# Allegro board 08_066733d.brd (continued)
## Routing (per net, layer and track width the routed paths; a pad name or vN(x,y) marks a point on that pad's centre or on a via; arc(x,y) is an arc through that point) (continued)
VDD_EXT: length 204.3
  TOP w0.14: U19.J10 48.21,36.93 v1(48.26,36.88) U19.K9 ; U19.P3 v1(51.56,33.88) ; v1(36.89,42.22) 37.47,42.22 R15.1 ; U2.7 v1(55.87,73.33) ; U19.N4 v1(49.97,34.38) U19.M4 ; U19.C6 v1(45.66,35.38) ; v1(39.5,42.22) 38.93,42.22 R14.1 ; U19.F5 v1(46.71,35.33) 46.66,35.38 U19.E6 ; U19.P5 v1(51.56,34.88)
  TOP w0.203: U1.H9 v1(32.22,54.94) ; U1.K14 v1(36.22,53.34) ; U1.H14 v1(35.42,54.94) ; U1.H13 v1(34.62,54.94) ; U1.M7 v1(30.62,51.74) ; U1.M14 v1(35.42,52.54) ; U1.H11 v1(33.02,54.94) ; U1.N7 v1(29.82,51.74) ; v1(29.82,54.14) 30.03,53.93 U1.K7 ; U1.N14 v1(35.42,51.74) ; U1.H7 v1(29.82,54.94)
  TOP w0.254: 54.87,68.97 U2.2 ; v2(30.48,14.99) 31.13,14.99 31.38,15.24 U16.15 ; 34.53,17.28 34.38,17.14 U16.4 ; U24.8 15.61,65.51 ; VR1.2 19.86,14.49 20.48,13.87 v1(20.48,13.5)
  TOP w0.267: 54.1,73.79 54.37,73.52 U2.10
  TOP w0.305: R75.1 57.78,21.21 v1(58.42,21.21) 59.19,21.21 R71.1 ; R30.1 v1(46.74,21.05) ; U17.3 47.07,15.17 C215.1 ; v1(37.97,33.78) 37.58,33.39 U25.14 ; v2(2.54,58.42) DS3.A ; U11.5 59.57,40.4 58.92,41.05 C180.1 58.8,41.2 v1(58.8,41.78) ; R136.1 v1(54.88,10.67) ; R136.1 54.22,10.02 53.72,9.52 53.72,7.56 53.98,7.31 U26.4 55.02,7.31 55.02,7.3 ; R136.1 v1(54.22,11.32) ; v1(58.8,28.07) 58.92,27.95 C182.1 58.93,27.3 59.56,26.67 59.56,25.73 U14.4 ; v1(54.22,5.19) R137.1 54.83,5.84 55.02,6.03 55.02,7.3 ; v1(56.52,7.28) C247.1 55.92,7.94 55.34,7.37 55.08,7.37 55.02,7.3 ; U22.14 31.67,33.39 v1(32,33.72) ; DS5.A 56.66,17.46 v1(58.04,17.46) ; 15.61,65.51 C179.1 v2(16.14,66.81) ; U18.3 56.46,57.98 56.77,58.28 56.77,59.69 56.58,59.88 U18.1 ; U12.14 25.77,38.59 26.29,39.12 v1(26.61,39.12) ; U13.5 59.5,30.79 v1(58.8,31.5) 58.8,32.27 C181.1 ; C218.1 42.93,14.99 43.1,15.17 U17.8 ; C64.1 v1(25.82,43.34) ; R29.1 v1(48.07,29.09) ; v2(4.45,58.42) DS2.A ; v1(21.15,44.07) 21.08,44.01 C157.1 ; v1(38.42,39.12) 37.89,39.12 37.58,38.81 U23.14 ; v1(24.22,43.34) C127.1 ; U4.2 v2(17.78,30.61) ; v2(6.35,58.42) DS1.A ; U21.14 25.84,33.34 v1(26.92,33.34) ; v2(5.71,80.9) 5.71,79.02 ; v1(5.71,8.38) R45.1 ; v1(32.22,43.34) C139.1 ; v2(16.89,78.74) 17.27,79.04 U7.14 ; v2(5.71,68.91) S1.C2 ; v2(6.35,99.57) DS8.A ; v2(19.3,9.65) R105.1 ; v2(4.45,99.57) DS7.A ; v1(22.62,43.34) C163.1 ; v1(21.22,43.34) 21.53,43.03 C80.1 ; v2(8.26,58.42) DS4.A ; v2(10.79,47.62) 10.79,47.62 R78.1 ; R70.1 v1(55.13,30.85) ; v1(32.07,39.12) 31.67,38.72 U20.14 ; R64.1 v2(12.51,67.75) ; v1(29.02,43.34) C135.1 ; R38.1 v1(53.23,19.69) ; C70.1 v1(30.62,43.34) ; v1(20.62,66.34) R60.1 ; v1(4.45,8.38) R41.1 ; v2(18.22,9.6) C210.1 ; v1(20.62,64.54) R61.1 ; v1(27.42,43.34) C143.1 ; v1(19.82,69.85) DS6.A
  TOP w0.381: U5.5 v2(15.5,42.86) ; U9.5 v2(19.82,42.86) ; U10.5 v2(11.18,42.86)
  TOP w0.508: v2(54.87,67.7) C254.1 54.87,68.97
  L2_PWR w0.508: TP1.1 57.45,63.87 ; TP1.1 55.32,63.87 ; TP1.1 55.32,61.74 ; TP1.1 57.45,61.74
  L4_SIG w0.381: v2(19.24,25.72) 19.75,25.21 19.75,17.4 20.48,16.66 v1(20.48,13.5) 19.3,12.32 v2(19.3,9.65) 19.25,9.6 v2(18.22,9.6)
  BOTTOM w0.14: v1(48.26,36.88) 47.73,36.88 C234.1 ; C235.1 v1(45.66,35.38)
  BOTTOM w0.305: C237.1 v1(51.56,33.88) ; v1(52.78,40.19) R63.1 R62.1 ; C239.1 31.42,38.73 31.81,39.12 v1(32.07,39.12) ; v1(32,33.72) 31.62,33.33 C241.1 ; C131.1 v1(24.22,43.34) ; C147.1 v1(41.91,42.86) ; C119.1 v1(42.99,42.86) ; v1(37.97,33.78) 37.84,33.78 37.52,33.46 C250.1 ; R121.1 v1(26.92,38.54) ; R46.1 v2(17.76,35.96) ; v1(26.61,39.12) 26.02,38.53 C238.1 ; v1(49.97,34.38) 49.97,33.66 49.65,33.33 C236.1 ; C233.1 v1(51.56,34.88) ; v2(20.64,32.07) 20.07,32.63 R114.1 ; v1(47.31,42.86) C115.1 ; v1(30.62,43.34) C95.1 ; v1(35.18,38.86) 35.18,38.52 R134.1 ; R87.1 v2(12.19,74.29) ; C85.1 v1(46.23,42.9) ; v1(21.15,44.7) 20.33,44.7 C54.1 20.33,44.07 v1(21.15,44.07) ; v1(22.22,34.32) 22.57,34.32 23.05,34.8 R119.1 ; v1(46.93,43.43) 47.74,43.43 C49.1 47.74,44.07 v1(46.93,44.07) ; v2(16.89,78.74) 16,78.74 C189.1 ; R81.1 v2(14.73,73.91) ; C111.1 v1(45.15,42.86) ; v1(29.82,54.94) C59.1 ; v1(35.42,54.94) 35.42,54.24 C90.1 ; C139.1 v1(32.22,43.34) ; v1(21.22,43.34) C103.1 ; R116.1 v1(33.91,28.2) ; v1(25.82,43.34) C99.1 ; v2(13.65,80.77) R83.1 ; R48.1 v2(10.92,37.09) ; v1(23.05,33.78) R122.1 ; v1(38.42,39.12) 38.17,39.12 C249.1 ; C135.1 v1(29.02,43.34) ; v2(12.19,79.88) R86.1 ; v1(44.07,42.86) 44.07,41.97 C107.1 ; C143.1 v1(27.42,43.34) ; v1(23.05,38.99) R118.1 ; R133.1 v1(26.92,33.34) 26.15,33.34 C240.1 ; C176.1 v2(17.78,30.61) ; C163.1 v1(22.62,43.34) ; R131.1 v1(23.05,28.84)
  BOTTOM w0.381: R47.1 v2(20.51,29.34) ; R132.1 v1(24.84,28.96) ; v2(16.57,25.72) 16.57,23.25 R143.1 ; C175.1 v2(19.82,42.86) ; v2(16.89,34.98) R139.1 ; Y5.4 C252.1 v2(16.14,31.62) ; Y6.4 15.31,27.34 C253.1 15.3,27.37 v2(16.12,27.37) ; v2(15.5,42.86) C173.1 ; R55.1 17.21,40.89 16.57,40.26 v2(16.57,39.56) ; v2(17.78,30.61) 16.92,29.74 R140.1 ; R51.1 v2(16.89,36.39) ; v2(11.18,42.86) 11.18,42.29 C174.1 ; v2(15.18,36.83) 15.18,36.01 C251.1 15.17,34.59 Y4.4 ; v1(36.65,34.22) 36.65,35 R138.1 36.5,35.11 R135.1 ; R53.1 v2(14.29,39.43) ; R120.1 25.15,34.54 v1(24.84,34.22)
  BOTTOM w0.508: v2(10.79,47.62) 9.65,48.77 9.65,57.02 v2(8.26,58.42) v2(6.35,58.42) v2(4.45,58.42) v2(2.54,58.42) 2.54,57.91 3.81,56.64 P6.1 ; R5.1 41.54,13.09 v2(41.53,13.08)
  vias: v2(8.26,6.98) v2(8.26,6.22) v2(10.16,6.98) v2(10.16,6.22) v2(17.46,26.86) v2(17.46,25.72) v2(18.35,26.86) v2(18.35,25.72) v2(19.24,26.86) v2(26.92,16.89) v2(26.92,16.13) v2(27.94,16.89) v2(27.94,16.13) v2(29.21,16.89) v2(29.21,16.13) v2(35.18,17.08) v2(35.81,16.64) v2(37.21,16.64) v2(39.5,13.08) v2(39.5,12.32) v2(39.5,11.56) v2(40.51,13.08) v2(40.51,12.32) v2(40.51,11.56) v2(41.53,12.32) v2(41.53,11.56) v2(52.33,73.41) v2(52.96,73.41) v2(57.91,63.12) v2(57.91,62.36) v2(57.91,61.59) v2(58.67,63.12) v2(58.67,62.36) v2(58.67,61.59)
VDD_INPUT: length 5.5
  BOTTOM w0.305: v2(12.83,19.43) 12.95,19.3 15.62,19.3 R96.1
  vias: v2(10.67,20.19) v2(10.67,19.43) v2(11.81,20.19) v2(11.81,19.43) v2(12.83,20.19) v2(23.24,19.43) v2(24.26,19.43) v2(25.27,19.43)
VDD_INT: length 117.1
  TOP w0.203: v1(35.42,49.34) U1.R13 ; U1.M10 v1(33.02,51.74) ; v1(33.02,53.34) U1.K10 ; U1.H10 v1(32.22,55.74) ; U1.U15 v1(37.02,47.74) ; U1.H8 v1(30.62,55.74) ; U1.M6 v1(29.02,52.54) ; U1.H12 v1(33.82,55.74) ; U1.R12 v1(34.62,49.34) ; U1.K6 v1(29.02,54.14) ; U1.T7 v1(29.82,48.54) U1.T6 ; v1(29.82,49.34) U1.R7 ; U1.U7 v1(29.82,47.74) ; U1.P6 v1(29.02,50.94) ; U1.R14 v1(36.22,49.34) ; U1.R10 v1(32.22,49.34) ; v1(29.82,55.74) U1.H6 ; U1.G13 v1(35.42,56.54) U1.G14 ; v1(34.62,55.74) U1.G12 ; U1.R11 v1(33.82,49.34) ; U1.M12 v1(34.62,52.54) ; U1.K12 v1(33.82,53.34) U1.K11 ; U1.K15 v1(37.02,53.34) ; U1.H15 v1(37.02,55.74) ; U1.N15 v1(37.02,50.94) ; v1(30.62,49.34) U1.R8 ; U1.M15 v1(37.02,51.74) ; U1.P15 v1(37.02,50.14) ; v1(31.42,49.34) U1.R9 ; U1.K13 v1(34.62,53.34) ; U1.G6 v1(29.02,55.74) ; U1.T15 v1(37.02,48.54) ; U1.M11 v1(33.82,51.74) ; U1.N6 v1(29.02,51.74) ; U1.T14 v1(36.22,48.54) ; U1.M13 v1(34.62,51.74)
  TOP w0.305: v1(23.02,61.34) C120.1 ; v2(32.88,11.81) C208.1 ; v1(23.02,58.14) C60.1 ; C164.1 22.77,50.29 v1(23.02,50.54) ; C100.1 22.49,52.94 v1(23.02,52.94) ; v1(23.02,49.14) C104.1 ; R44.1 v2(1.91,8.38) ; R107.2 v2(35.94,9.52) ; v1(23.02,46.34) C86.1 ; v1(33.42,63.14) C93.1 ; v1(25.22,63.14) C78.1 ; v1(30.62,63.14) C83.1 ; v1(23.02,56.54) C116.1 ; C209.2 v2(37.21,9.52) ; R99.2 27.31,14.99 26.92,14.6 v2(26.92,13.59) ; v1(23.02,55.34) C91.1 ; v1(23.02,54.14) C96.1 ; v1(32.02,63.14) C88.1 ; v1(27.92,63.14) C73.1 ; v2(34.67,12) R101.1 ; v1(23.02,59.74) C81.1 ; v1(29.22,63.14) C68.1
  TOP w0.508: TP2.1 33.2,27.04 ; TP2.1 31.06,27.04 ; TP2.1 33.2,24.91 ; TP2.1 31.06,24.91
  L2_PWR w0.508: TP2.1 33.2,27.04 ; TP2.1 31.06,27.04 ; TP2.1 33.2,24.91 ; TP2.1 31.06,24.91
  BOTTOM w0.14: v1(33.82,49.34) 33.34,48.86 33.34,43.86 33.21,43.73 33.21,39.81 33.91,39.12 33.91,38.66 33.72,38.47 33.72,38.17 33.21,37.66 33.21,36.19 33.66,35.75 33.66,33.15 34.04,32.77 34.04,31.37 33.72,31.05 33.08,31.05 32.17,30.14 31.18,30.14 30.82,29.78 30.82,28.47 30.04,27.69 28.64,27.69 28.13,27.18 28.13,26.98 28.7,26.42 28.7,26.16
  BOTTOM w0.305: v1(29.82,49.34) 29.59,49.57 29.59,49.81 C152.1 ; v1(33.02,51.74) v1(33.82,51.74) v1(34.62,51.74) v1(34.62,52.54) v1(34.62,53.34) v1(33.82,53.34) v1(33.02,53.34) ; C60.1 v1(23.02,58.14) ; C50.1 18.92,50.54 v1(19.62,50.54) ; C164.1 22.77,50.29 v1(23.02,50.54) ; C132.1 31.62,49.78 31.62,49.54 v1(31.42,49.34) ; C136.1 36.22,49.7 v1(36.22,49.34) ; v1(30.62,49.34) C108.1 ; v1(37.02,53.34) v1(37.02,51.74) ; v2(1.91,8.38) v2(1.91,7.62) v2(1.02,7.62) v2(1.02,8.38) v2(1.02,9.14) v2(1.02,9.91) ; C96.1 v1(23.02,54.14) ; v2(14.22,54.61) 15.35,54.61 L1.1 15.31,53.98 v2(14.22,53.98) ; C100.1 22.49,52.94 v1(23.02,52.94) ; C212.1 28.7,25.53 28.7,26.16 ; v1(23.02,51.74) 22.84,51.56 C61.1 ; C76.1 36.12,56.54 v1(35.42,56.54) ; v1(29.02,55.74) C65.1 ; v1(23.02,47.74) C148.1 ; C55.1 17.35,56.34 17.65,56.04 v1(17.82,56.04) ; C128.1 35.42,49.7 v1(35.42,49.34) ; C120.1 v1(23.02,61.34) ; C91.1 v1(23.02,55.34) ; v1(33.82,55.74) C112.1 ; C81.1 v1(23.02,59.74) ; C116.1 v1(23.02,56.54) ; C104.1 v1(23.02,49.14) ; C71.1 v1(23.02,46.34)
  BOTTOM w0.508: TP2.1 33.2,27.04 ; TP2.1 31.06,24.91 ; TP2.1 33.2,24.91 ; TP2.1 31.06,27.04
  vias: v2(30.42,25.78) v2(30.86,26.99) v2(30.86,24.13) v2(32.13,24.13) v2(33.4,25.02) v2(33.4,24.13) v2(33.46,26.92) v2(33.85,25.78)
VDD_PLL: length 18.8
  TOP w0.305: U1.K8 v1(31.42,54.14) U1.K9 ; U1.M8 v1(31.42,52.54) U1.M9
  BOTTOM w0.305: C244.1 31.42,53.24 v1(31.42,52.54) 31.42,51.92 C46.1 ; C244.1 31.42,53.44 v1(31.42,54.14) ; C244.1 30.35,53.34 C242.1 30.11,53.34 24.36,53.34 C243.1 24.25,53.45 22.77,53.45 22.76,53.45 21.88,53.45 21.88,53.46 21.76,53.46 21.76,53.45 20.88,53.45 20.88,53.46 19.64,53.46 C47.1 17.89,53.44 L1.2
VDD_REF: length 206.1
  TOP w0.203: U1.P12 v1(34.62,50.14) ; U1.P11 v1(33.82,50.14) ; U1.P10 v1(32.22,50.14)
  TOP w0.305: C87.1 v1(46.22,45.34) ; v1(46.22,51.74) C77.1 ; v1(54.74,25.97) 54.74,25.38 R33.1 ; v1(6.98,8.26) R43.1 ; v1(3.17,8.38) R42.1 ; v1(46.22,48.54) C129.1 ; C109.1 34.99,43.71 v1(35.42,44.14) ; R39.1 v1(55.07,23.18) ; v1(43.02,45.34) C62.1 ; C82.1 v1(43.02,48.54) ; v1(46.22,50.14) C67.1 ; R32.1 v1(44.95,27.81) ; v1(33.82,43.34) C149.1 ; v1(43.02,50.14) C133.1 ; v1(46.22,46.94) C72.1
  TOP w0.508: v2(61.47,50.67) v2(61.47,51.43) ; v2(59.69,51.43) R16.1
  TOP w0.635: FL2.1 59.25,54.93 v2(59.69,54.48)
  L6_PWR w0.508: 60.02,57.99 TP4.1 62.15,57.99
  L7_SIG w0.305: v2(35.94,12) 35.94,15.05 35.37,15.62 34.66,15.62 34.35,15.93 34.35,18.61 34.29,18.67 34.29,21.27 35.67,22.65 35.67,33.51 35.14,34.04 35.14,37.15 36.8,38.82 36.8,40.86 35.75,41.91 35.75,43.81 v1(35.42,44.14)
  BOTTOM w0.305: v1(46.22,45.34) C125.1 ; v2(59.69,51.43) 59.69,50.55 58.8,49.66 56.9,49.66 53.4,46.16 53.4,44.7 49.66,40.96 49.66,39.55 49.35,39.24 ; C92.1 v1(46.22,51.74) ; C97.1 v1(43.02,45.34) ; C101.1 v1(46.22,46.94) ; C105.1 v1(46.22,50.14) ; C149.1 v1(33.82,43.34) ; v1(49.32,48.54) 50.12,48.54 C57.1 50.72,48.54 v1(51.62,48.54) ; C113.1 v1(43.02,50.14) ; C137.1 43.9,52.52 v1(43.92,52.54) ; v1(43.02,48.54) C145.1 ; v1(43.02,46.94) C121.1 ; C141.1 v1(46.22,48.54)
  BOTTOM w0.381: v1(35.42,44.14) 35.42,43.44 C52.1 36.22,43.44 v1(36.22,44.14) ; v1(3.17,8.38) 4,9.21 7.94,9.21 9.97,11.24 19.11,11.24 20.89,13.02 22.35,13.02 24.7,10.67 34.67,10.67 35.21,11.21 35.21,11.21 35.94,11.94 v2(35.94,12) ; 49.35,39.24 45.34,39.24 44.58,38.48 44.58,33.85 45.02,33.4 47.43,33.4 47.88,32.96 47.88,30.16 46.36,28.64 46.36,23.18 47.62,21.91 47.62,18.03 49.02,16.64 49.02,10.41 48.39,9.78 38.1,9.78 37.47,10.41 35.62,10.41 35.11,9.91 24.13,9.91 22.86,11.18 20.45,11.18 19.75,10.48 10.35,10.48 8.13,8.26 v1(6.98,8.26)
  vias: v2(60.45,57.53) v2(60.45,56.77) v2(60.45,56.01) v2(61.47,57.53) v2(61.47,56.77) v2(61.47,56.01)
AUDIO_CLK: length 74.8
  TOP w0.14: R36.2 v1(55.1,22.1)
  L8_SIG w0.127: v1(8.26,31.88) 10.2,31.88 12.17,29.91 18.2,29.91 21.33,26.78 26.73,26.78 30.28,23.24 33.53,23.24 34.48,24.19 34.48,26.18 35.64,27.34 37.1,27.34 37.29,27.53 37.29,28.1 38.47,29.29 43.45,29.29 44.91,30.75 50.81,30.75 51.12,31.05 51.94,31.05 52.2,30.8 52.2,30.23 50.67,28.7 50.67,22.88 51.92,21.63 52.69,21.63 53.15,22.1 v1(55.1,22.1)
  BOTTOM w0.14: J3.40 8.25,31.88 v1(8.26,31.88) 8.95,31.88 9.33,32.26 9.33,34.8 10.14,35.6 R141.2
CLK1: length 69
  TOP w0.14: R35.2 v1(52.08,28.38)
  L8_SIG w0.127: v1(10.99,35.12) 17.7,41.83 20.02,41.83 20.59,42.41 30.58,42.41 31.45,41.53 34.2,41.53 34.78,40.96 38.8,40.96 40.11,39.65 50.33,39.65 53.66,36.32 53.66,35.79 53.66,29.96 v1(52.08,28.38)
  BOTTOM w0.14: 9.97,31.37 10.22,31.62 10.22,34.35 v1(10.99,35.12) ; 9.97,31.37 10.22,31.11 10.22,29.34 10.38,29.18 R142.2 ; 9.97,31.37 6.91,31.37 J3.42
CLK2: length 65.9
  TOP w0.14: v1(50.35,18.92) 50.35,19.63 R37.2
  L4_SIG w0.127: v1(50.35,18.92) 50.35,19.82 49.75,20.42 48.48,20.42 47.62,21.27 47.62,26.03 v2(44.32,29.34)
  L8_SIG w0.127: v2(44.32,29.34) 43.94,28.96 38.61,28.96 37.62,27.97 37.62,27.4 37.24,27.01 35.78,27.01 34.81,26.04 34.81,24.06 33.66,22.91 30.14,22.91 26.63,26.42 21.21,26.42 18.82,28.8 13.4,28.8 12.72,29.49 9.63,29.49 v1(8.26,30.86)
  BOTTOM w0.14: J3.44 8,30.61 v1(8.26,30.86) 8.76,30.86 9.14,30.48 9.14,29.08 9.84,28.38 11.3,28.38 11.87,27.81 R144.2
CON_RESET_IN*: length 78.8
  TOP w0.14: U11.2 56.26,38.73 55.82,38.29 v1(54.61,38.29) 53.92,38.29 53.53,37.9 53.53,32 52.51,30.99 52.07,30.99 v1(51.5,30.42)
  L4_SIG w0.127: v1(8.51,14.22) 8.51,19.79 10.05,21.33 10.05,21.35 10.1,21.4 10.1,27.9 10.52,28.32 v2(12.19,28.32)
  L8_SIG w0.127: v2(12.19,28.32) 12.19,27.56 14.83,24.92 22.45,24.92 23.93,23.44 27.87,23.44 28.73,22.58 33.8,22.58 35.14,23.92 35.14,25.91 35.92,26.68 36.26,26.68 37.38,26.68 37.95,27.26 37.95,27.83 38.75,28.63 46.15,28.63 47.94,30.42 v1(51.5,30.42)
  BOTTOM w0.14: R62.2 v1(54.61,38.29) ; J3.96 6.91,14.22 v1(8.51,14.22)
DAI0_PIN01: length 55.7
  TOP w0.203: v1(35.42,47.74) U1.U13
  L4_SIG w0.127: v1(53.21,15.11) 50.61,15.11 47.24,18.48 47.24,23.43 44.45,26.23 44.45,28.32 43.73,29.04 43.73,29.88 44.69,30.85 44.69,37.22 42.56,39.36 42.56,40.98 41.14,42.43 41.14,43.47 39.84,44.77 39.15,44.77 39.02,44.89 39.02,47.14 38.82,47.34 35.82,47.34 v1(35.42,47.74)
  L8_SIG w0.127: v1(61.72,13.72) 61.09,14.35 53.98,14.35 v1(53.21,15.11)
  BOTTOM w0.14: J1.3 61.47,13.46 v1(61.72,13.72)
DAI0_PIN02: length 50
  TOP w0.203: v1(37.02,46.14) U1.W15
  L4_SIG w0.127: v1(58.8,13.59) 49.98,13.59 45.28,18.29 45.28,23.37 42.55,26.1 42.55,28.32 41.91,28.96 41.91,32.98 42.55,33.61 42.55,35.05 41.91,35.68 41.91,38.44 40.26,40.09 40.26,41.65 40.07,41.84 40.07,43.03 39.41,43.69 38.61,43.69 37.42,44.87 37.42,45.74 v1(37.02,46.14)
  BOTTOM w0.14: 59.31,14.1 59.31,14.1 ; 59.31,14.1 59.31,14.1 ; 59.31,14.1 J1.5 ; 59.31,14.1 v1(58.8,13.59)
DAI0_PIN03: length 47.7
  TOP w0.203: v1(37.82,45.34) U1.Y16
  L5_SIG w0.127: v1(37.82,45.34) 37.82,44.6 41.28,41.15 41.28,31.37 44.2,28.45 45.33,28.45 45.66,28.12 45.66,25.68 49.55,21.78 51.76,21.78 53.66,19.88 57.59,19.88 57.79,19.68 59.56,19.68 60.45,18.8 60.45,16.13 v1(61.72,14.86)
  BOTTOM w0.14: v1(61.72,14.86) 60.41,14.86 J1.7
DAI0_PIN04: length 62.5
  TOP w0.203: v1(35.42,46.14) U1.W13
  L4_SIG w0.127: v1(61.72,15.62) 61.09,14.99 61.09,12.83 58.42,10.16 54.74,10.16 52.2,12.7 49.47,12.7 41.85,20.32 40.7,20.32 36.55,24.47 36.55,26.39 40.87,30.71 40.87,37.93 39.18,39.62 39.18,40.58 35.81,43.94 35.81,45.75 v1(35.42,46.14)
  BOTTOM w0.14: v1(61.72,15.62) 61.47,15.37 J1.9
DAI0_PIN05: length 47.4
  TOP w0.203: v1(37.02,46.94) U1.V15
  L5_SIG w0.127: v1(58.8,15.87) 59.56,16.64 59.56,18.8 59.05,19.3 57.6,19.3 57.4,19.49 54.8,19.49 54.55,19.24 53.07,19.24 51.55,20.76 50.1,20.76 44.45,26.42 44.45,27.5 40.83,31.12 40.83,40 38.16,42.67 38.16,43.05 37.42,43.8 37.42,46.54 v1(37.02,46.94)
  BOTTOM w0.14: J1.11 58.93,16 v1(58.8,15.87)
DAI0_PIN06: length 51
  TOP w0.203: v1(38.62,45.34) U1.Y17
  L4_SIG w0.127: v1(58.8,16.76) 59.44,16.13 59.44,14.86 59.05,14.48 50.55,14.48 46.29,18.73 46.29,23.62 43.4,26.52 43.4,28.8 42.67,29.53 42.67,30.67 43.75,31.75 43.75,32.7 44.32,33.27 44.32,37.02 41.02,40.32 41.02,42.04 40.81,42.25 40.81,43.33 39.75,44.39 38.81,44.39 38.62,44.58 v1(38.62,45.34)
  BOTTOM w0.14: J1.13 58.93,16.64 v1(58.8,16.76)
DAI0_PIN07: length 53.7
  TOP w0.203: v1(37.82,46.14) U1.W16
  L4_SIG w0.127: v1(58.8,17.53) 59.94,16.38 59.94,14.73 59.31,14.1 50.16,14.1 45.79,18.47 45.79,23.49 42.99,26.29 42.99,28.51 42.29,29.21 42.29,32.89 42.98,33.58 42.98,35.1 42.24,35.84 42.24,38.57 40.64,40.17 40.64,41.85 40.45,42.04 40.45,43.22 39.61,44.06 38.68,44.06 38.22,44.52 38.22,45.74 v1(37.82,46.14)
  BOTTOM w0.14: J1.15 59.05,17.27 v1(58.8,17.53)
DAI0_PIN08: length 59.6
  TOP w0.203: v1(36.22,46.94) U1.V14
  L4_SIG w0.127: v1(36.22,46.94) 36.63,46.53 36.63,45.08 38.43,43.31 39.12,43.31 39.31,43.12 39.31,42.7 39.07,42.45 39.07,41.71 39.88,40.89 39.88,39.94 41.53,38.29 41.53,26.54 44.77,23.3 44.77,18.16 49.72,13.21 53.09,13.21 55.37,10.92 58.17,10.92 60.45,13.21 60.45,16.38 v1(61.72,17.65)
  BOTTOM w0.14: J1.17 61.47,17.91 v1(61.72,17.65)
DAI0_PIN09: length 49.6
  TOP w0.203: v1(35.42,48.54) U1.T13
  L5_SIG w0.127: v1(58.04,18.16) 56.96,17.08 48.83,17.08 45.28,20.64 45.28,23.12 40.07,28.33 40.07,36.32 37.08,39.31 37.08,40.96 35.82,42.22 35.82,48.14 v1(35.42,48.54)
  BOTTOM w0.14: J1.19 59.31,18.54 58.93,18.16 v1(58.04,18.16)
DAI0_PIN10: length 45.7
  TOP w0.203: v1(36.22,47.74) U1.U14
  L5_SIG w0.127: v1(58.04,18.8) 57.02,17.78 53.59,17.78 51.27,20.1 50.3,20.1 40.45,29.95 40.45,39.31 36.62,43.14 36.62,47.34 v1(36.22,47.74)
  BOTTOM w0.14: J1.21 60.15,19.3 58.55,19.3 v1(58.04,18.8)
DAI0_PIN11: length 44.6
  TOP w0.203: v1(37.82,46.94) U1.V16
  L5_SIG w0.127: v1(61.72,19.43) 60.45,20.7 55.69,20.7 54.93,21.46 54.48,21.46 52.45,23.49 49.06,23.49 46.1,26.46 46.1,29.21 44.77,30.54 44.77,32.64 42.53,34.87 42.53,40.65 38.22,44.97 38.22,46.54 v1(37.82,46.94)
  BOTTOM w0.14: v1(61.72,19.43) 61.34,19.81 J1.23
DAI0_PIN12: length 40.5
  TOP w0.203: v1(39.42,45.34) U1.Y18
  L5_SIG w0.127: v1(61.72,20.19) 60.2,21.72 56.64,21.72 55.75,22.61 54.99,22.61 53.53,24.07 53.53,24.7 52.64,25.59 50.21,25.59 45.29,30.51 45.29,33.09 44.2,34.19 44.2,39.72 39.42,44.49 v1(39.42,45.34)
  BOTTOM w0.14: v1(61.72,20.19) 61.47,20.45 J1.25
DAI0_PIN13: length 49.1
  TOP w0.203: v1(37.82,50.94) U1.N16
  L5_SIG w0.127: v1(61.72,20.95) 62.23,21.46 62.23,22.73 61.21,23.75 61.21,24.76 58.93,27.05 57.85,27.05 56.45,28.45 54.1,28.45 51.18,31.37 51.18,31.94 50.36,32.76 50.36,34.73 50.32,34.77 50.32,41.95 47.24,45.02 47.24,49.02 46.63,49.64 44.82,49.64 43.12,51.34 38.22,51.34 v1(37.82,50.94)
  BOTTOM w0.14: v1(61.72,20.95) 61.59,21.08 J1.27
DAI0_PIN14: length 46.5
  TOP w0.203: v1(38.62,49.34) U1.R17
  L5_SIG w0.127: v1(38.62,49.34) 39.02,48.94 41.66,48.94 41.93,49.21 43.15,49.21 44.02,48.34 44.02,45.14 45.58,43.58 45.58,39.99 45.15,39.56 45.15,34.8 46.48,33.46 46.48,31.43 50.3,27.61 52.65,27.61 54.1,26.16 54.1,25.46 55.13,24.43 56.46,24.43 58.04,22.86 60.58,22.86 v1(61.72,21.72)
  BOTTOM w0.14: v1(61.72,21.72) 61.72,21.72 ; 61.72,21.72 61.21,21.72 ; 61.72,21.72 61.21,21.72 ; 61.21,21.72 J1.29
DAI0_PIN15: length 46
  TOP w0.203: v1(38.62,50.14) U1.P17
  L5_SIG w0.127: v1(38.62,50.14) 39.02,50.54 41.02,50.54 41.22,50.74 43.06,50.74 43.26,50.54 44.52,49.28 46.36,49.28 46.86,48.77 46.86,44.89 49.72,42.04 49.72,34.86 49.4,34.54 49.4,31.88 54.17,27.11 55.18,27.11 55.44,27.37 56.83,27.37 v1(61.72,22.48)
  BOTTOM w0.14: v1(61.72,22.48) 61.6,22.35 J1.31
DAI0_PIN16: length 41.1
  TOP w0.203: v1(39.42,48.54) U1.T18
  L5_SIG w0.127: v1(39.42,48.54) 39.82,48.14 42.82,48.14 43.52,47.44 43.52,44.77 44.7,43.58 44.7,34.14 45.62,33.23 45.62,30.64 49.66,26.61 52.28,26.61 56.54,22.35 v1(58.42,22.35)
  BOTTOM w0.14: J1.33 59.06,22.99 v1(58.42,22.35)
DAI0_PIN17: length 41.2
  TOP w0.203: v1(39.42,49.34) U1.R18
  L5_SIG w0.127: v1(58.42,23.37) 55.42,26.37 54.95,26.37 54.59,26.73 54.04,26.73 52.83,27.94 50.48,27.94 49.85,28.57 49.85,29.53 47.75,31.62 47.75,34.51 47.24,35.02 47.24,39.62 46.66,40.21 46.66,43.07 44.35,45.38 44.35,48.78 43.54,49.59 41.87,49.59 41.72,49.74 39.82,49.74 v1(39.42,49.34)
  BOTTOM w0.14: v1(58.42,23.37) 58.67,23.62 J1.35
DAI0_PIN18: length 46.1
  TOP w0.203: v1(40.22,47.74) U1.U19
  L7_SIG w0.127: v1(57.79,48.51) 57.79,47.62 59.56,45.85 59.56,26.16 v1(61.72,24)
  L8_SIG w0.127: v1(57.79,48.51) 52.25,48.51 51.49,47.74 v1(40.22,47.74)
  BOTTOM w0.14: J1.37 61.47,24.26 v1(61.72,24)
DAI0_PIN19: length 45.3
  TOP w0.14: U1.Y19 40.86,44.7 55.11,44.7 56.89,46.48 v1(60.07,46.48)
  L7_SIG w0.127: v1(61.72,24.76) 60.07,26.42 v1(60.07,46.48)
  BOTTOM w0.14: J1.39 61.59,24.89 v1(61.72,24.76)
DAI0_PIN20: length 47.1
  TOP w0.203: v1(39.42,46.14) U1.W18
  L7_SIG w0.127: v1(60.07,47.24) 60.58,46.73 60.58,26.67 v1(61.72,25.53)
  L8_SIG w0.127: v1(39.42,46.14) 39.83,45.73 41.22,45.73 41.59,46.1 48.75,46.1 49.62,45.22 52.71,45.22 54.72,47.24 v1(60.07,47.24)
  BOTTOM w0.14: 61.21,25.53 J1.41 ; 61.21,25.53 v1(61.72,25.53) 61.72,25.53 61.21,25.53
DAI1_PIN01: length 52.1
  TOP w0.203: v1(37.82,52.54) U1.L16
  L5_SIG w0.127: v1(40.07,24.83) 40.96,23.94 42.35,23.94 44.64,21.65 44.64,20.38 51.94,13.08 v1(55.12,13.08)
  BOTTOM w0.14: J1.4 55.5,13.46 v1(55.12,13.08) ; v1(40.07,24.83) 40.73,25.49 40.73,27.43 40.41,27.75 40.41,42.9 38.22,45.09 38.22,52.14 v1(37.82,52.54)
DAI1_PIN02: length 56
  TOP w0.203: v1(41.02,54.94) U1.J20
  L4_SIG w0.127: v1(41.02,54.94) 44.69,54.94 45.37,54.26 47.21,54.26 50.16,51.31 50.16,43.31 51.17,42.3 51.17,38.77 53.7,36.23 54.7,36.23 56.11,34.82 56.11,24.56 55.98,24.43 55.04,24.43 54.55,23.94 54.55,22.02 57.02,19.55 57.02,16.89 v1(58.8,15.11)
  BOTTOM w0.14: J1.6 57.79,14.1 v1(58.8,15.11)
DAI1_PIN03: length 53.6
  TOP w0.203: v1(39.42,54.14) U1.K18
  L4_SIG w0.127: v1(39.42,54.14) 39.82,53.74 44.92,53.74 48.01,50.65 48.01,46.8 49.28,45.53 49.28,43.12 50.51,41.88 50.51,38.41 50.67,38.25 50.67,38.23 53.47,35.43 53.47,33.61 54.67,32.41 54.67,28.32 53.15,26.79 53.15,25.4 53.72,24.83 53.72,21.72 54.29,21.15 54.29,20.51 54.79,20.01 55.62,20.01 56.52,19.11 56.52,16.64 v1(58.04,15.11)
  BOTTOM w0.14: J1.8 57.66,14.73 v1(58.04,15.11)
DAI1_PIN04: length 51.1
  TOP w0.203: v1(38.62,52.54) U1.L17
  L4_SIG w0.127: v1(38.62,52.54) 39.02,52.14 42.92,52.14 44.26,50.8 44.26,45.87 45.49,44.64 47.12,44.64 47.5,44.26 47.5,43.43 49.39,41.54 49.39,38.07 52.48,34.98 52.48,33.2 53,32.68 53,28.11 51.31,26.42 51.31,25.57 51.67,25.2 51.67,21.89 54.42,19.14 54.42,15.81 v1(55.12,15.11)
  BOTTOM w0.14: v1(55.12,15.11) 55.37,15.37 J1.10
DAI1_PIN05: length 51.3
  TOP w0.203: v1(38.62,53.34) U1.L18
  L4_SIG w0.127: v1(38.62,53.34) U1.L18 42.72,52.94 44.77,50.89 44.77,46.86 45.78,45.85 46.42,45.85 48.12,44.15 48.12,43.32 49.77,41.67 49.77,38.15 52.81,35.12 52.81,33.34 53.33,32.82 53.33,27.9 51.67,26.25 51.67,25.67 52.01,25.33 52.01,22.77 52.83,21.95 52.83,21.23 54.51,19.56 55.5,19.56 55.75,19.3 55.75,16.64 v1(55.12,16)
  BOTTOM w0.14: J1.12 55.5,16 v1(55.12,16)
DAI1_PIN06: length 51
  TOP w0.203: v1(39.42,51.74) U1.M18
  L4_SIG w0.127: v1(39.42,51.74) 42.72,51.74 43.94,50.52 43.94,45.8 46.74,43 46.74,42.42 48.64,40.51 48.64,37.59 50.53,35.71 50.53,33.38 52.64,31.26 52.64,28.33 52.06,27.75 51.18,27.75 50.67,27.24 50.67,22.39 52.8,20.26 52.8,19.51 53.05,19.26 53.51,19.26 54.05,18.72 54.05,16.71 v1(53.21,15.87)
  BOTTOM w0.14: v1(53.21,15.87) 53.98,16.64 J1.14
DAI1_PIN07: length 48.8
  TOP w0.203: v1(39.42,50.94) U1.N18
  L4_SIG w0.127: v1(39.42,50.94) 39.82,50.54 41.28,50.54 41.75,50.07 41.75,46.01 44.5,43.26 44.5,42.88 46.86,40.51 46.86,37.02 47.12,36.77 47.12,34.89 46.82,34.59 46.82,33.57 49.21,31.18 50.13,31.18 51.18,30.12 51.18,28.77 49.29,26.87 49.29,25.95 48.58,25.24 48.58,22.57 53.05,18.1 53.53,18.1 53.72,17.91 53.72,17.14 v1(53.21,16.64)
  BOTTOM w0.14: v1(53.21,16.64) 53.59,17.02 55.12,17.02 55.38,17.27 J1.16
DAI1_PIN08: length 47
  TOP w0.203: v1(39.42,50.14) U1.P18
  L4_SIG w0.127: v1(53.21,17.53) 51.94,17.53 50.85,18.62 50.85,19.83 47.96,22.72 47.96,25.09 48.96,26.09 48.96,27.05 50.85,28.94 50.85,29.92 50.16,30.61 49.15,30.61 45.85,33.91 45.85,34.61 46.16,34.92 46.16,39.95 43.5,42.62 43.5,43.43 41.42,45.51 41.42,49.04 40.72,49.74 39.82,49.74 v1(39.42,50.14)
  BOTTOM w0.14: v1(53.21,17.53) 54.99,17.53 55.37,17.91 J1.18
DAI1_PIN09: length 47.3
  TOP w0.203: v1(38.62,51.74) U1.M17
  L8_SIG w0.127: v1(55.12,18.29) 53.09,18.29 51.82,19.56 50.8,19.56 49.97,20.38 48.2,20.38 43.75,24.83 v1(40.83,24.83)
  BOTTOM w0.14: v1(38.62,51.74) 39.02,51.34 39.02,45.05 40.75,43.32 40.75,27.89 41.07,27.57 41.07,25.07 v1(40.83,24.83) ; v1(55.12,18.29) 55.37,18.54 J1.20
DAI1_PIN10: length 46.3
  TOP w0.203: v1(37.82,51.74) U1.M16
  L8_SIG w0.127: v1(55.12,19.05) 54.04,19.05 53.85,19.24 52.71,19.24 51.94,20 50.86,20 49.59,21.28 48.06,21.28 43.82,25.53 42.01,25.53 v1(40.07,27.47)
  BOTTOM w0.14: J1.22 55.25,19.18 v1(55.12,19.05) ; v1(37.82,51.74) 37.42,51.34 37.42,44.94 40.07,42.29 v1(40.07,27.47)
DAI1_PIN11: length 49.6
  TOP w0.203: v1(38.62,50.94) U1.N17
  L4_SIG w0.127: v1(38.62,50.94) 39.02,51.34 42.52,51.34 43.56,50.3 43.56,45.34 45.72,43.18 45.72,42.61 48.26,40.07 48.26,37.43 48.65,37.04 48.65,35.5 47.75,34.61 47.75,33.53 48.13,33.15 50.23,33.15 52.01,31.37 52.01,29.12 49.66,26.77 49.66,22.03 52.9,18.8 v1(53.21,18.8)
  BOTTOM w0.14: v1(53.21,18.8) 54.36,19.81 J1.24
DAI1_PIN12: length 40.5
  TOP w0.203: v1(40.22,48.54) U1.T19
  L8_SIG w0.127: v1(55.25,20.45) 52.64,20.45 51.21,21.88 48.99,21.88 44.45,26.42 42.67,26.42 v1(42.1,26.99)
  BOTTOM w0.14: J1.26 55.25,20.45 v1(55.25,20.45) ; v1(40.22,48.54) 39.82,48.14 39.82,45.02 41.1,43.74 41.1,28.03 42.1,27.03 v1(42.1,26.99)
DAI1_PIN13: length 48
  TOP w0.203: v1(40.22,54.94) U1.J19
  L4_SIG w0.127: v1(54.74,20.88) 54.74,21.34 54.17,21.91 54.17,26.25 55.75,27.84 55.75,34.67 54.52,35.9 53.56,35.9 50.84,38.63 50.84,42.13 49.78,43.18 49.78,51.22 47.09,53.91 45.28,53.91 44.65,54.54 40.62,54.54 v1(40.22,54.94)
  BOTTOM w0.14: J1.28 54.94,21.08 v1(54.74,20.88)
DAI1_PIN14: length 46.8
  TOP w0.203: v1(41.02,55.74) U1.H20
  L4_SIG w0.127: v1(41.02,55.74) 45.99,55.74 46.76,54.97 47.65,54.97 50.88,51.74 50.88,43.61 51.87,42.62 51.87,39 53.98,36.89 55.05,36.89 56.87,35.08 56.87,22.96 v1(55.63,21.72)
  BOTTOM w0.14: v1(55.63,21.72) J1.30
DAI1_PIN15: length 48.4
  TOP w0.203: v1(38.62,54.14) U1.K17
  L4_SIG w0.127: v1(53.85,20.95) 53.21,21.59 53.21,22.03 52.34,22.91 52.34,25.41 52.64,25.72 52.64,26.75 53.66,27.77 53.66,32.96 53.14,33.48 53.14,35.26 50.15,38.24 50.15,41.75 48.45,43.46 48.45,44.32 47.12,45.66 47.12,49.97 46.23,50.86 45.34,50.86 44.72,51.48 44.72,52.75 44.13,53.34 39.42,53.34 v1(38.62,54.14)
  BOTTOM w0.14: v1(53.85,20.95) 53.85,21.59 54.86,22.61 55.44,22.61 55.69,22.35 J1.32
DAI1_PIN16: length 46.8
  TOP w0.203: v1(39.42,54.94) U1.J18
  L4_SIG w0.127: v1(55.5,24) 56.13,24 56.45,24.32 56.45,34.99 54.88,36.56 53.84,36.56 51.5,38.9 51.5,42.44 50.55,43.39 50.55,51.45 47.39,54.61 46.48,54.61 45.75,55.34 39.82,55.34 v1(39.42,54.94)
  BOTTOM w0.14: v1(55.5,24) 55.5,23.37 55.5,23.36 55.5,23.24 55.75,22.99 J1.34
DAI1_PIN17: length 47.9
  TOP w0.203: v1(40.22,55.74) U1.H19
  L4_SIG w0.127: v1(58.42,24.26) 57.2,25.48 57.2,36.02 55.44,37.78 53.66,37.78 52.2,39.24 52.2,52.26 48.77,55.69 46.68,55.69 46.24,56.14 40.62,56.14 v1(40.22,55.74)
  BOTTOM w0.14: J1.36 57.79,23.62 v1(58.42,24.26)
DAI1_PIN18: length 46.4
  TOP w0.203: v1(41.02,56.54) U1.G20
  L4_SIG w0.127: v1(41.02,56.54) 42.02,56.54 42.42,56.94 46.13,56.94 46.98,56.09 48.84,56.09 52.53,52.4 52.53,41.2 53.34,40.39 53.34,39.88 54.42,38.8 54.99,38.8 57.53,36.26 57.53,25.78 v1(58.42,24.89)
  BOTTOM w0.14: J1.38 57.79,24.26 v1(58.42,24.89)
DAI1_PIN19: length 34.8
  TOP w0.14: v1(41.02,48.54) U1.T20
  L7_SIG w0.127: v1(41.02,48.54) 41.79,47.77 43.54,47.77 44.04,47.27 44.04,45.32 44.59,44.77 44.59,33.58 46.23,31.94 46.23,30.1 49.72,26.61 52.26,26.61 53.97,24.89 v1(55.63,24.89)
  BOTTOM w0.14: J1.40 v1(55.63,24.89)
DAI1_PIN20: length 34.7
  TOP w0.203: v1(42.22,48.54) 41.72,48.04 40.92,48.04 U1.U20
  L7_SIG w0.127: v1(55.5,25.65) 55.5,26.03 54.99,26.54 54.29,26.54 53.09,27.75 49.47,27.75 48.63,28.59 48.63,29.54 47.82,30.35 47.82,34.6 47.24,35.18 47.24,36.62 45.72,38.14 45.72,44.32 44.45,45.59 44.45,47.53 43.88,48.1 42.66,48.1 v1(42.22,48.54)
  BOTTOM w0.14: v1(55.5,25.65) 56.55,25.65 J1.42
DMC0_A00: length 41.4
  TOP w0.203: v1(37.02,58.94) U1.C15 ; U8.N3 v1(36.22,74.34)
  L4_SIG w0.127: v1(36.22,74.34) 36.22,75.54 37.22,76.54 42.02,76.54 42.82,75.74 42.82,65.74 42.62,65.54 42.42,65.54 42.22,65.74 41.82,65.74 41.62,65.54 41.62,65.34 42.02,64.94 42.02,62.94 41.82,62.74 41.62,62.74 41.42,62.94 41.42,63.34 41.22,63.54 41.02,63.54 40.82,63.34 40.82,62.94 40.62,62.74 38.62,62.74 37.42,61.54 37.42,59.34 v1(37.02,58.94)
  BOTTOM w0.14: v1(36.22,74.34) 36.62,74.34 36.82,74.54 36.82,74.74 36.62,74.94 36.22,74.94 36.02,75.14 36.02,75.34 36.22,75.54 39.22,75.54 39.82,76.14 41.98,76.14 RN1.1
DMC0_A01: length 41.3
  TOP w0.203: v1(37.02,78.34) 37.39,77.97 U8.P7 ; v1(37.82,61.34) U1.A16
  L8_SIG w0.127: v1(37.82,61.34) 37.82,61.94 38.02,62.14 40.42,62.14 40.62,62.34 40.62,62.54 40.42,62.74 38.42,62.74 38.22,62.94 38.22,63.54 38.42,63.74 39.02,63.74 39.22,63.54 40.42,63.54 40.62,63.74 40.62,79.74 39.62,80.74 37.62,80.74 37.42,80.54 37.42,78.74 v1(37.02,78.34)
  BOTTOM w0.14: v1(37.02,78.34) 37.42,78.74 39.02,78.74 39.42,79.14 39.42,79.94 39.62,80.14 40.22,80.14 40.42,80.34 40.42,80.54 40.22,80.74 40.22,80.94 40.42,81.14 40.82,81.14 41.02,80.94 41.02,80.74 40.83,80.55 40.83,80.13 41.07,79.89 RN3.2
DMC0_A02: length 41.3
  TOP w0.203: U8.P3 v1(37.02,75.14) ; v1(36.22,58.14) U1.E14
  L4_SIG w0.127: v1(36.22,58.14) 36.62,58.54 36.62,59.34 37.02,59.74 37.02,61.74 38.22,62.94 38.22,63.74 38.42,63.94 40.02,63.94 40.62,64.54 40.62,66.34 40.82,66.54 41.22,66.54 42.02,67.34 42.02,67.94 41.62,68.34 41.62,68.94 42.02,69.34 42.02,69.74 41.62,70.14 41.62,70.54 42.02,70.94 42.02,71.34 41.62,71.74 41.62,72.54 42.02,72.94 42.02,73.34 41.62,73.74 41.62,73.94 42.02,74.34 42.02,74.54 41.82,74.74 39.82,74.74 39.62,74.94 39.62,75.14 39.82,75.34 40.62,75.34 40.82,75.14 41.42,75.14 41.62,75.34 41.62,75.54 41.42,75.74 37.62,75.74 v1(37.02,75.14)
  BOTTOM w0.14: RN2.2 41.52,73.49 41.42,73.39 41.42,72.14 41.02,71.74 39.82,71.74 39.42,72.14 39.42,73.54 39.02,73.94 38.22,73.94 v1(37.02,75.14)
DMC0_A03: length 41.2
  TOP w0.14: v1(39.42,63.14) 39.42,62.74 39.62,62.54 41.82,62.54 42.02,62.34 42.02,62.14 41.82,61.94 36.82,61.94 36.62,61.74 U1.A15
  TOP w0.203: U8.N2 v1(36.22,73.54)
  L4_SIG w0.127: v1(36.22,73.54) U8.N2 36.62,75.34 37.42,76.14 41.82,76.14 42.42,75.54 42.42,66.94 41.02,65.54 41.02,64.14 40.42,63.54 39.82,63.54 v1(39.42,63.14)
  BOTTOM w0.14: RN5.2 36.77,70.14 36.97,70.34 37.82,70.34 38.02,70.54 38.02,70.74 37.62,71.14 37.42,71.14 37.22,70.94 37.02,70.94 36.82,71.14 36.82,71.34 37.02,71.54 37.12,71.54 37.32,71.74 37.32,71.84 36.62,72.54 36.62,73.86 36.54,73.94 36.32,73.94 36.22,73.84 v1(36.22,73.54)
DMC0_A04: length 41.2
  TOP w0.203: U8.P8 37.39,78.77 v1(37.02,79.14) ; v1(35.42,59.74) U1.C14
  L8_SIG w0.127: v1(35.42,59.74) 35.02,60.14 35.02,61.74 34.42,62.34 34.42,66.54 36.22,68.34 36.22,68.6 36.05,68.77 35.82,68.77 34.62,67.57 34.22,67.57 34.05,67.74 34.05,67.94 36.63,70.52 36.63,70.74 36.44,70.94 36.22,70.94 34.42,69.14 34.22,69.14 34.02,69.34 34.02,69.54 36.62,72.14 36.62,78.74 v1(37.02,79.14)
  BOTTOM w0.14: RN4.1 37.91,84.54 39.17,84.54 39.37,84.34 39.37,82.54 39.17,82.34 38.02,82.34 37.82,82.14 37.82,80.74 37.42,80.34 37.42,79.54 v1(37.02,79.14)
DMC0_A05: length 41.3
  TOP w0.203: U8.P2 v1(37.02,73.54) ; v1(37.02,58.14) U1.D15
  L4_SIG w0.127: v1(37.02,58.14) 36.62,57.74 35.02,57.74 34.82,57.54 34.82,56.54 35.02,56.34 35.02,54.74 34.82,54.54 34.42,54.54 34.22,54.74 34.22,58.34 34.42,58.54 34.82,58.54 35.02,58.74 35.02,60.74 35.42,61.14 35.42,62.54 36.02,63.14 36.02,65.54 36.62,66.14 36.62,67.14 37.02,67.54 37.02,69.74 37.22,69.94 38.22,69.94 38.42,70.14 38.42,70.34 38.22,70.54 37.22,70.54 37.02,70.74 37.02,70.94 37.22,71.14 38.22,71.14 38.42,71.34 38.42,71.54 38.22,71.74 37.02,71.74 36.62,72.14 36.62,73.14 v1(37.02,73.54)
  BOTTOM w0.14: RN5.3 37.27,69.79 37.42,69.94 38.22,69.94 38.42,69.74 38.82,69.74 39.02,69.94 39.42,69.94 39.62,70.14 39.62,70.34 39.42,70.54 38.82,70.54 37.82,71.54 37.82,71.94 37.42,72.34 37.42,73.14 v1(37.02,73.54)
DMC0_A06: length 41.1
  TOP w0.203: v1(37.82,79.14) 38.19,78.77 U8.R8 ; v1(36.22,60.54) U1.B14
  L8_SIG w0.127: v1(36.22,60.54) 35.82,60.94 35.82,66.54 36.22,66.94 39.22,66.94 39.42,67.14 39.42,67.54 39.22,67.74 38.62,67.74 38.42,67.54 37.42,67.54 37.22,67.74 37.22,68.14 37.42,68.34 39.22,68.34 39.42,68.54 39.42,68.8 39.22,69 38.42,69 38.22,69.2 38.22,69.74 38.42,69.94 39.22,69.94 39.42,70.14 39.42,70.54 39.22,70.74 38.02,70.74 37.82,70.94 37.82,71.34 38.02,71.54 39.22,71.54 39.42,71.74 39.42,76.54 38.62,77.34 38.62,78.34 v1(37.82,79.14)
  BOTTOM w0.14: RN3.4 41.82,81.03 41.82,81.14 42.02,81.34 42.22,81.34 42.42,81.54 42.42,81.74 42.22,81.94 38.42,81.94 38.22,81.74 38.22,79.54 v1(37.82,79.14)
DMC0_A07: length 41.1
  TOP w0.203: U8.R2 v1(37.82,73.54) ; v1(36.22,59.74) U1.B15
  L4_SIG w0.127: v1(37.82,73.54) U8.R2 40.42,73.94 40.62,73.74 40.62,73.54 40.42,73.34 39.22,73.34 39.02,73.14 39.02,72.94 39.22,72.74 40.42,72.74 40.62,72.54 40.62,72.34 40.42,72.14 39.42,72.14 39.22,71.94 39.22,71.74 39.42,71.54 40.42,71.54 40.62,71.34 40.62,71.14 40.42,70.94 39.42,70.94 39.22,70.74 39.22,70.54 39.42,70.34 40.42,70.34 40.62,70.14 40.62,69.94 40.42,69.74 39.82,69.74 39.62,69.54 39.62,69.34 39.82,69.14 40.42,69.14 40.62,68.94 40.62,68.74 40.42,68.54 39.62,68.54 39.42,68.34 39.42,68.14 39.62,67.94 40.42,67.94 40.62,67.74 40.62,67.54 40.42,67.34 39.62,67.34 39.42,67.14 39.42,64.94 39.22,64.74 37.22,64.74 37.02,64.54 37.02,64.14 37.42,63.74 37.42,62.74 36.62,61.94 U1.B15 v1(36.22,59.74)
  BOTTOM w0.14: RN5.4 37.91,68.83 38.1,69.02 38.28,69.02 38.4,69.14 38.84,69.14 39.02,68.96 39.82,68.96 40.02,69.16 40.02,70.74 39.82,70.94 39.02,70.94 38.22,71.74 38.22,73.14 v1(37.82,73.54)
DMC0_A08: length 41.1
  TOP w0.203: v1(36.22,61.34) U1.A14 ; v1(38.62,79.14) 38.99,78.77 U8.T8
  L8_SIG w0.127: v1(36.22,61.34) 36.82,61.34 37.02,61.54 37.02,61.94 36.82,62.14 36.42,62.14 36.22,62.34 36.22,63.74 36.42,63.94 37.22,63.94 37.42,64.14 37.42,64.34 37.22,64.54 36.42,64.54 36.22,64.74 36.22,64.94 36.42,65.14 38.02,65.14 38.22,65.34 38.22,65.74 38.02,65.94 36.42,65.94 36.22,66.14 36.22,66.34 36.42,66.54 39.62,66.54 39.82,66.74 39.82,76.94 39.02,77.74 39.02,80.14 38.82,80.34 38.42,80.34 38.22,80.14 38.22,79.54 v1(38.62,79.14)
  BOTTOM w0.14: RN3.3 41.62,80.39 41.42,80.59 41.42,81.34 41.22,81.54 38.82,81.54 38.62,81.34 38.62,81.04 38.76,80.9 38.98,80.9 39.22,81.14 39.62,81.14 39.82,80.94 39.82,80.74 39.62,80.54 39.22,80.54 39.02,80.34 39.02,79.54 v1(38.62,79.14)
DMC0_A09: length 41.1
  TOP w0.203: U8.R3 v1(37.82,75.14) ; v1(35.42,58.94) U1.C13
  L4_SIG w0.127: v1(35.42,58.94) 35.82,59.34 35.82,62.14 36.42,62.74 36.42,64.74 36.82,65.14 38.82,65.14 39.02,65.34 39.02,65.94 38.82,66.14 37.42,66.14 37.22,66.34 37.22,66.54 37.42,66.74 38.82,66.74 39.02,66.94 39.02,67.14 38.82,67.34 37.62,67.34 37.42,67.54 37.42,67.74 37.62,67.94 38.82,67.94 39.02,68.14 39.02,68.27 38.82,68.47 37.62,68.47 37.42,68.67 37.42,68.82 37.62,69.02 38.62,69.02 38.82,69.22 38.82,71.94 38.42,72.34 37.62,72.34 37.42,72.54 37.42,74.54 37.62,74.74 39.02,74.74 39.22,74.94 39.22,75.14 39.02,75.34 38.22,75.34 v1(37.82,75.14)
  BOTTOM w0.14: v1(37.82,75.14) 39.02,75.14 39.42,74.74 39.82,74.74 40.02,74.94 40.02,75.54 40.22,75.74 40.42,75.74 40.62,75.54 40.62,75.34 40.42,75.14 40.42,74.74 40.62,74.54 40.82,74.54 41,74.71 41,75.54 41.19,75.74 41.42,75.74 41.62,75.54 41.62,75.34 41.42,75.14 41.42,74.77 41.56,74.63 RN2.4
DMC0_A10: length 41.1
  TOP w0.203: v1(34.62,78.34) 34.99,77.97 U8.L7 ; v1(33.82,59.74) U1.C11
  L8_SIG w0.127: v1(34.62,78.34) 34.22,77.94 32.22,77.94 31.82,77.54 31.82,76.34 32.02,76.14 32.22,76.14 32.42,76.34 32.42,77.14 32.62,77.34 32.82,77.34 33.02,77.14 33.02,75.94 33.42,75.54 34.82,75.54 35.02,75.34 35.02,71.94 33.02,69.94 33.02,66.17 33.53,65.66 33.53,65.28 33.4,65.15 32.38,65.15 32.26,65.02 32.26,64.77 32.38,64.64 33.4,64.64 33.53,64.52 33.53,64.26 33.4,64.13 32.01,64.13 31.88,64 31.88,63.75 32,63.63 32.38,63.63 32.51,63.5 32.51,62.65 33.42,61.74 33.42,60.14 v1(33.82,59.74)
  BOTTOM w0.14: RN7.1 34.16,84.29 34.16,82.86 34.34,82.68 34.84,82.68 35.22,82.3 35.22,81.72 34.84,81.34 34.42,81.34 34.22,81.14 34.22,78.04 34.32,77.94 34.52,77.94 34.62,78.04 v1(34.62,78.34)
DMC0_A11: length 41.2
  TOP w0.203: v1(37.82,78.34) 38.19,77.97 U8.R7 ; v1(35.42,60.54) U1.B13
  L8_SIG w0.127: v1(35.42,60.54) 35.42,62.14 35.02,62.54 35.02,66.34 36.82,68.14 36.82,69.54 37.42,70.14 37.42,75.54 37.02,75.94 37.02,77.16 37.22,77.36 37.62,77.36 37.82,77.16 37.82,76.14 38.22,75.74 38.22,72.34 38.42,72.14 38.82,72.14 39.02,72.34 39.02,75.94 38.22,76.74 U8.R7 v1(37.82,78.34)
  BOTTOM w0.14: v1(37.82,78.34) 37.82,77.94 37.42,77.54 36.42,77.54 36.22,77.34 36.22,77.14 36.42,76.94 38.82,76.94 39.22,77.34 40.67,77.34 41.16,77.83 RN1.4
DMC0_A12: length 41.2
  TOP w0.203: v1(33.02,59.74) U1.B11 ; U8.N7 36.59,77.97 v1(36.22,78.34)
  L8_SIG w0.127: v1(33.02,59.74) 32.62,60.14 32.62,60.83 32.89,61.11 32.89,61.45 31.8,62.54 31.5,62.85 31.5,66.01 31.62,66.14 32.42,66.14 32.62,66.34 32.62,66.54 32.42,66.74 31.42,66.74 31.22,66.94 31.22,67.14 31.42,67.34 32.22,67.34 32.62,67.74 32.62,70.34 34.22,71.94 34.22,74.74 33.82,75.14 32.82,75.14 32.42,75.54 31.22,75.54 31.02,75.74 31.02,78.54 31.22,78.74 35.82,78.74 v1(36.22,78.34)
  BOTTOM w0.14: v1(36.22,78.34) 36.62,78.74 36.62,80.34 37.27,80.99 37.27,82.59 37.42,82.74 38.33,82.74 38.53,82.94 38.53,83.61 38.39,83.75 37.48,83.75 37.27,83.96 RN4.2
DMC0_A13: length 41.1
  TOP w0.14: U1.A13 35.02,61.54 34.22,62.34 34.22,64.74 34.42,64.94 34.62,64.94 34.82,64.74 34.82,62.74 35.02,62.54 35.62,62.54 35.94,62.86 35.94,65.54 36.08,65.68 36.28,65.68 36.42,65.54 36.42,62.94 36.82,62.54 37.22,62.54 v1(37.82,63.14)
  TOP w0.203: U8.T3 v1(38.62,74.34)
  L4_SIG w0.127: v1(37.82,63.14) 37.82,63.94 38.22,64.34 39.42,64.34 39.82,64.74 39.82,66.54 40.22,66.94 40.82,66.94 41.22,67.34 41.22,73.94 40.82,74.34 v1(38.62,74.34)
  BOTTOM w0.14: RN2.3 41.22,73.99 41.02,73.79 41.02,73.54 40.82,73.34 40.48,73.34 40.28,73.14 40.28,72.94 40.48,72.74 40.82,72.74 41.02,72.54 41.02,72.34 40.82,72.14 40.02,72.14 39.82,72.34 39.82,73.54 40.22,73.94 40.22,74.14 40.02,74.34 v1(38.62,74.34)
DMC0_A14: length 41.3
  TOP w0.203: U8.T7 v1(39.42,78.34) ; v1(32.22,59.74) U1.C10
  L8_SIG w0.127: v1(32.22,59.74) U1.C10 35.62,59.34 35.82,59.54 35.82,59.94 36.02,60.14 36.82,60.14 37.42,60.74 37.42,63.54 38.22,64.34 39.02,64.34 39.22,64.14 40.02,64.14 40.22,64.34 40.22,64.74 40.02,64.94 39.22,64.94 39.02,65.14 39.02,65.74 39.22,65.94 40.02,65.94 40.22,66.14 40.22,79.54 40.02,79.74 39.62,79.74 39.42,79.54 v1(39.42,78.34)
  BOTTOM w0.14: v1(39.42,78.34) 39.42,77.94 39.62,77.74 39.82,77.74 40.02,77.94 40.02,79.54 40.22,79.74 40.42,79.74 40.62,79.54 40.62,78.74 40.42,78.54 40.42,78.34 40.62,78.14 41.42,78.14 41.62,78.34 41.62,78.54 41.42,78.74 41.2,78.74 41,78.94 41,79.19 41.2,79.39 41.87,79.39 RN3.1
DMC0_A15: length 40.9
  TOP w0.203: v1(34.62,59.74) U1.C12 ; v1(35.42,78.34) 35.79,77.97 U8.M7
  L8_SIG w0.127: v1(34.62,59.74) 34.22,60.14 34.22,61.74 33.02,62.94 33.02,63.34 33.22,63.54 33.82,63.54 34.02,63.74 34.02,65.94 33.42,66.54 33.42,69.74 35.82,72.14 35.82,74.54 35.42,74.94 35.42,75.14 35.62,75.34 36.02,75.34 36.22,75.54 36.22,75.74 36.02,75.94 33.82,75.94 33.62,76.14 33.62,76.34 33.82,76.54 36.02,76.54 36.22,76.74 36.22,76.94 36.02,77.14 34.62,77.14 34.42,76.94 33.62,76.94 33.42,77.14 33.42,77.34 33.62,77.54 35.22,77.54 35.42,77.74 v1(35.42,78.34)
  BOTTOM w0.14: RN4.4 36.13,83.88 35.99,83.74 35.28,83.74 35.08,83.54 35.08,83.34 35.28,83.14 35.62,83.14 35.82,82.94 35.82,81.54 35.22,80.94 35.02,80.94 34.62,80.54 34.62,78.94 34.82,78.74 35.02,78.74 v1(35.42,78.34)
DMC0_BA0: length 41.1
  TOP w0.203: v1(34.62,58.94) U1.D13 ; U8.M2 v1(35.42,73.54)
  L4_SIG w0.127: v1(35.42,73.54) 35.82,73.14 35.82,72.34 36.22,71.94 36.22,71.74 36.02,71.54 35.62,71.54 35.42,71.34 35.42,71.14 35.62,70.94 36.22,70.94 36.42,70.74 36.42,70.54 36.22,70.34 35.62,70.34 35.42,70.14 35.42,69.94 35.62,69.74 36.22,69.74 36.42,69.54 36.42,69.34 36.22,69.14 35.62,69.14 35.42,68.94 35.42,68.54 35.62,68.34 36.42,68.34 36.62,68.14 36.62,67.94 36.42,67.74 34.42,67.74 34.22,67.54 34.22,67.34 34.42,67.14 35.82,67.14 36.02,66.94 36.02,66.54 35.82,66.34 35.02,66.34 34.82,66.54 34.42,66.54 34.22,66.34 34.22,65.94 34.42,65.74 34.82,65.74 35.02,65.54 35.02,65.34 34.82,65.14 34.42,65.14 34.22,64.94 34.22,64.74 34.42,64.54 35.22,64.54 35.42,64.34 35.42,64.14 35.22,63.94 34.42,63.94 34.22,63.74 34.22,63.54 34.42,63.34 34.82,63.34 35.02,63.14 35.02,62.74 34.82,62.54 34.02,62.54 33.82,62.34 33.82,62.14 34.02,61.94 34.82,61.94 35.02,61.74 35.02,61.34 34.82,61.14 34.42,61.14 34.22,60.94 34.22,59.34 v1(34.62,58.94)
  BOTTOM w0.14: RN5.1 36.22,68.84 36.22,69.39 36.37,69.54 36.37,69.74 36.22,69.89 36.22,70.14 36.62,70.54 36.62,70.74 36.52,70.84 36.32,70.84 36.22,70.94 36.22,71.54 36.32,71.64 36.52,71.64 36.62,71.74 36.62,71.94 36.22,72.34 36.02,72.34 35.82,72.54 35.82,73.74 35.62,73.94 35.22,73.94 35.02,73.74 35.02,73.24 35.12,73.14 35.32,73.14 35.42,73.24 v1(35.42,73.54)
DMC0_BA1: length 41.2
  TOP w0.203: U8.N8 36.59,78.77 v1(36.22,79.14) ; v1(36.22,58.94) U1.D14
  L8_SIG w0.127: v1(36.22,79.14) 36.62,79.54 36.62,80.54 37.22,81.14 37.62,81.14 37.62,81.14 39.82,81.14 41.02,79.94 41.02,61.94 40.82,61.74 38.42,61.74 38.22,61.54 38.22,60.34 38.02,60.14 37.42,60.14 v1(36.22,58.94)
  BOTTOM w0.14: v1(36.22,79.14) 35.82,79.54 35.22,79.54 35.02,79.74 35.02,80.34 35.22,80.54 35.62,80.54 35.82,80.74 35.82,80.94 36.02,81.14 36.5,81.14 36.7,81.34 36.7,81.54 36.5,81.74 36.34,81.74 36.22,81.86 36.22,82.04 36.32,82.14 36.65,82.14 36.78,82.27 36.78,82.38 36.62,82.54 36.62,82.74 36.82,82.94 37.02,82.94 37.22,83.14 37.22,83.34 36.77,83.79 RN4.3
DMC0_BA2: length 41.3
  TOP w0.203: U8.M3 v1(35.42,74.34) ; v1(36.22,57.34) U1.E15
  L4_SIG w0.127: v1(35.42,74.34) 35.02,73.94 35.02,69.74 34.82,69.54 34.02,69.54 33.82,69.34 33.82,69.14 34.02,68.94 34.82,68.94 35.02,68.74 35.02,68.54 34.82,68.34 34.02,68.34 33.82,68.14 33.82,62.94 33.02,62.14 33.02,61.34 33.42,60.94 33.42,58.74 33.22,58.54 32.82,58.54 32.62,58.34 32.62,53.94 32.82,53.74 35.62,53.74 35.82,53.94 35.82,56.94 v1(36.22,57.34)
  BOTTOM w0.14: RN1.2 41.22,76.69 41.07,76.54 39.62,76.54 39.02,75.94 35.42,75.94 35.22,75.74 35.22,75.14 35.42,74.94 v1(35.42,74.34)
DMC0_CAS*: length 41.2
  TOP w0.203: U8.K3 34.19,74.71 v1(33.82,74.34) ; v1(37.82,58.94) U1.C17
  L8_SIG w0.127: v1(37.82,58.94) 38.22,58.54 38.22,57.14 38.02,56.94 30.42,56.94 30.22,57.14 30.22,61.74 29.82,62.14 29.82,72.14 30.22,72.54 30.22,74.14 30.82,74.74 33.42,74.74 v1(33.82,74.34)
  BOTTOM w0.14: RN6.3 34.07,69.39 34.22,69.54 34.84,69.54 35.09,69.29 35.22,69.29 35.42,69.49 35.42,70.54 35.02,70.94 35.02,71.14 35.42,71.54 35.42,71.74 35.22,71.94 34.42,71.94 34.22,72.14 34.22,73.94 v1(33.82,74.34)
DMC0_CK: length 33.7
  TOP w0.203: U8.J7 33.39,77.97 v1(33.02,78.34) ; v1(38.62,61.34) U1.A17
  L4_SIG w0.076: v1(33.02,78.34) 33.27,78.09 33.27,77.74 33.53,77.48 42.42,77.48 44.2,75.7 44.2,66.43 43.82,66.05 43.82,63 42.8,61.99 39.88,61.99 39.5,61.61 39.5,61.35 39.24,61.1 38.99,61.1 v1(38.62,61.34)
  BOTTOM w0.14: R3.1 33.02,77.44 v1(33.02,78.34)
DMC0_CK*: length 33.7
  TOP w0.203: v1(39.42,60.54) U1.A18 ; U8.K7 v1(33.82,78.34)
  L4_SIG w0.076: v1(39.42,60.54) 39.42,60.9 39.75,61.23 39.75,61.48 40.01,61.73 42.93,61.73 44.07,62.88 44.07,65.93 44.45,66.31 44.45,75.83 42.55,77.74 33.66,77.74 33.53,77.86 33.53,78.05 v1(33.82,78.34)
  BOTTOM w0.14: R3.2 33.82,77.34 v1(33.82,78.34)
DMC0_CKE: length 41.3
  TOP w0.203: v1(33.82,79.94) 34.19,79.57 U8.K9 ; v1(38.62,60.54) U1.B17
  L8_SIG w0.127: v1(38.62,60.54) 39.02,60.94 41.42,60.94 42.02,61.54 42.02,70.94 41.42,71.54 41.42,80.14 40.02,81.54 35.42,81.54 v1(33.82,79.94)
  BOTTOM w0.14: v1(33.82,79.94) 33.82,81.54 34.02,81.74 34.62,81.74 34.82,81.94 34.82,82.14 34.62,82.34 34.22,82.34 34.02,82.14 32.89,82.14 32.77,82.27 32.77,82.42 32.89,82.55 33.15,82.55 33.27,82.68 33.27,82.9 33.15,83.02 32.89,83.02 32.77,83.15 32.77,83.44 32.89,83.57 33.44,83.57 33.56,83.69 RN7.2
DMC0_CS0*: length 41.2
  TOP w0.203: v1(37.82,59.74) U1.C16 ; U8.L2 v1(34.62,73.54)
  L4_SIG w0.127: v1(37.82,59.74) 38.22,60.14 38.22,61.74 38.82,62.34 42.22,62.34 42.62,62.74 42.62,64.14 43.22,64.74 43.22,75.94 42.22,76.94 37.02,76.94 35.82,75.74 35.82,75.14 35.42,74.74 35.02,74.74 34.62,74.34 v1(34.62,73.54)
  BOTTOM w0.14: RN6.4 34.71,68.54 34.82,68.54 35.15,68.21 35.15,67.87 35.25,67.77 35.45,67.77 35.62,67.94 35.62,68.34 35.42,68.54 35.42,69.01 35.82,69.41 35.82,71.94 35.42,72.34 34.82,72.34 34.62,72.54 v1(34.62,73.54)
DMC0_DQ00: length 33.3
  TOP w0.203: U8.E3 30.19,74.77 v1(29.82,75.14) ; U1.A5 v1(28.22,61.34)
  L4_SIG w0.127: 26.7,62 26.16,62.54 26.16,63.37 26.42,63.63 26.42,63.88 26.16,64.13 26.16,67.44 26.29,67.56 29.34,67.56 29.46,67.69 29.46,67.94 29.34,68.07 26.29,68.07 26.16,68.2 26.16,68.45 26.29,68.58 27.05,68.58 27.18,68.71 27.18,70.23 27.3,70.36 27.56,70.36 27.69,70.23 27.69,68.71 27.81,68.58 29.34,68.58 29.46,68.71 29.46,68.96 29.34,69.09 28.83,69.09 28.7,69.21 28.7,69.47 28.83,69.6 29.34,69.6 29.46,69.72 29.46,69.98 29.34,70.1 28.7,70.1 28.57,70.23 28.57,70.48 28.7,70.61 28.96,70.61 29.02,70.68 29.02,71.94 28.62,72.34 28.62,74.54 28.82,74.74 29.42,74.74 v1(29.82,75.14)
  L4_SIG w0.14: v1(28.22,61.34) 28.57,61.69 28.57,61.85 28.42,62 26.7,62
DMC0_DQ01: length 33.4
  TOP w0.203: U8.F7 v1(30.62,77.54) ; U1.C7 v1(29.82,58.94)
  L4_SIG w0.127: v1(29.82,58.94) 29.42,59.34 26.22,59.34 25.82,59.74 25.02,59.74 24.38,60.38 24.38,71.94 24.58,72.13 24.63,72.13 24.64,72.14 26.04,72.14 26.16,72.26 26.16,72.52 26.04,72.64 24.76,72.64 24.64,72.77 24.64,73.02 24.76,73.15 26.04,73.15 26.16,73.28 26.16,76.28 26.42,76.54 30.82,76.54 31.02,76.74 31.02,77.14 v1(30.62,77.54)
DMC0_DQ02: length 33.4
  TOP w0.203: U1.D7 v1(30.62,58.14) ; v1(31.42,73.54) 31.05,73.91 31.05,73.91 U8.F2
  L4_SIG w0.127: v1(30.62,58.14) 31.02,57.74 31.02,57.14 30.82,56.94 29.18,56.94 28.98,56.74 28.98,56.34 29.18,56.14 30.82,56.14 31.02,55.94 31.02,55.54 30.82,55.34 29.62,55.34 29.42,55.14 29.42,54.74 29.62,54.54 31.62,54.54 31.82,54.74 31.82,58.34 31.62,58.54 31.22,58.54 31.02,58.74 31.02,62.06 31.57,62.62 31.57,63.5 31.83,63.75 32.35,63.75 32.62,64.02 32.62,72.94 32.42,73.14 31.82,73.14 v1(31.42,73.54)
DMC0_DQ03: length 33.4
  TOP w0.203: v1(31.42,78.34) 31.05,78.71 31.05,78.71 U8.F8 ; U1.B7 v1(29.82,60.54)
  L4_SIG w0.127: v1(29.82,60.54) 29.42,60.14 25.62,60.14 25.42,60.34 25.42,61.74 24.83,62.33 24.83,70.45 24.99,70.61 25.78,70.61 25.91,70.74 25.91,70.99 25.78,71.12 25.02,71.12 24.89,71.25 24.89,71.5 25.02,71.63 26.89,71.63 27.02,71.75 27.02,74.54 26.62,74.94 26.62,75.74 27.02,76.14 31.82,76.14 32.22,76.54 32.22,77.54 v1(31.42,78.34)
DMC0_DQ04: length 33.4
  TOP w0.203: U8.H3 32.59,74.77 v1(32.22,75.14) ; U1.B6 v1(29.02,60.54)
  L4_SIG w0.127: v1(32.22,75.14) 31.82,74.74 31.82,74.14 32.02,73.94 32.42,73.94 32.62,74.14 U8.H3 32.82,74.94 32.82,75.54 32.62,75.74 27.42,75.74 27.22,75.54 27.22,75.14 27.82,74.54 27.82,72.39 27.57,72.14 27.57,71.98 28.42,71.13 28.42,70.94 28.22,70.74 28.07,70.74 27.57,71.25 27.43,71.25 26.67,70.49 26.67,70.23 26.54,70.1 25.78,70.1 25.65,69.98 25.65,69.72 25.78,69.6 26.54,69.6 26.67,69.47 26.67,69.21 26.54,69.09 25.78,69.09 25.65,68.96 25.65,62.29 26.22,61.72 26.22,61.14 26.42,60.94 28.62,60.94 v1(29.02,60.54)
DMC0_DQ05: length 33.4
  TOP w0.203: U8.H8 32.59,78.77 v1(32.22,79.14) ; U1.B8 v1(31.42,60.54)
  L4_SIG w0.127: v1(31.42,60.54) 31.82,60.94 31.82,62.34 32.49,63.01 32.49,63.35 33.02,63.88 33.02,72.54 33.42,72.94 33.42,75.54 32.62,76.34 32.62,80.24 32.32,80.54 28.02,80.54 27.82,80.34 27.82,79.04 28.02,78.84 28.32,78.84 28.52,79.04 28.52,79.34 28.72,79.54 31.82,79.54 v1(32.22,79.14)
DMC0_DQ06: length 33.3
  TOP w0.203: v1(31.42,74.34) 31.79,73.97 U8.G2 ; U1.C6 v1(29.82,59.74)
  L4_SIG w0.127: v1(29.82,59.74) 30.22,59.34 30.42,59.34 30.62,59.54 30.62,59.69 30.24,60.07 30.24,60.2 30.6,60.57 30.6,60.7 30.22,61.08 30.22,62.14 31.19,63.11 31.19,63.97 31.37,64.15 32.13,64.15 32.26,64.27 32.26,64.9 32.13,65.02 31.88,65.02 31.75,64.9 31.75,64.77 31.62,64.64 31.24,64.64 31.11,64.77 31.11,65.02 31.5,65.4 31.5,65.62 30.82,66.29 30.82,66.54 31.02,66.74 31.61,66.74 31.75,66.6 31.75,66.29 31.88,66.17 32.13,66.17 32.22,66.26 32.22,67.14 32.02,67.34 30.93,67.34 30.73,67.54 30.73,67.74 30.93,67.94 32.02,67.94 32.22,68.14 32.22,68.34 32.02,68.54 30.82,68.54 30.62,68.74 30.62,68.85 30.82,69.05 31.62,69.05 31.82,69.25 31.82,69.54 31.62,69.74 31.19,69.74 30.99,69.94 30.99,70.14 31.19,70.34 32.02,70.34 32.22,70.54 32.22,70.74 32.02,70.94 30.82,70.94 30.62,71.14 30.62,71.41 30.75,71.54 32.02,71.54 32.22,71.74 32.22,71.94 32.02,72.14 31.22,72.14 31.02,72.34 31.02,73.94 v1(31.42,74.34)
DMC0_DQ07: length 33.4
  TOP w0.203: U8.H7 32.59,77.97 v1(32.22,78.34) ; U1.C8 v1(30.62,58.94)
  L4_SIG w0.127: v1(32.22,78.34) 31.82,78.74 31.02,78.74 29.42,77.14 26.31,77.14 23.94,74.76 23.94,60.02 24.82,59.14 25.62,59.14 26.22,58.54 30.22,58.54 v1(30.62,58.94)
DMC0_DQ08: length 33.5
  TOP w0.203: U1.A8 v1(30.62,61.34) ; v1(29.02,78.34) 29.39,77.97 U8.D7
  BOTTOM w0.14: v1(30.62,61.34) 30.22,60.94 27.22,60.94 27.02,61.14 27.02,61.61 26.78,61.85 24.87,61.85 24.62,62.1 24.62,77.72 24.84,77.94 26.82,77.94 27.82,78.94 27.82,80.36 27.53,80.64 27.53,80.91 27.65,81.02 28.49,81.02 28.62,80.89 28.62,80.77 28.49,80.64 28.49,80.44 28.62,80.31 28.62,78.74 v1(29.02,78.34)
DMC0_DQ09: length 33.4
  TOP w0.203: v1(32.22,58.94) U1.D9 ; v1(29.02,74.34) 28.65,74.71 28.65,74.71 U8.C3
  BOTTOM w0.14: v1(29.02,74.34) 29.42,73.94 30.06,73.94 30.22,74.1 30.42,74.1 30.62,73.9 30.62,73.34 30.42,73.14 28.82,73.14 28.62,72.94 28.62,72.54 28.82,72.34 30.02,72.34 30.22,72.14 30.22,71.74 30.02,71.54 29.22,71.54 29.02,71.74 28.42,71.74 28.22,71.54 28.22,70.34 28.62,69.94 30.02,69.94 30.22,69.74 30.22,69.2 30.02,69 28.42,69 28.22,68.8 28.22,68.54 28.42,68.34 30.23,68.34 30.35,68.21 30.35,67.94 29.97,67.56 29.97,64.13 30.1,64.01 30.35,64.01 30.48,64.13 30.48,64.52 30.61,64.64 30.86,64.64 30.99,64.52 30.99,64.13 31.11,64.01 32.64,64.01 32.89,63.75 32.89,62.88 33.42,62.36 33.42,59.54 33.22,59.34 32.62,59.34 v1(32.22,58.94)
